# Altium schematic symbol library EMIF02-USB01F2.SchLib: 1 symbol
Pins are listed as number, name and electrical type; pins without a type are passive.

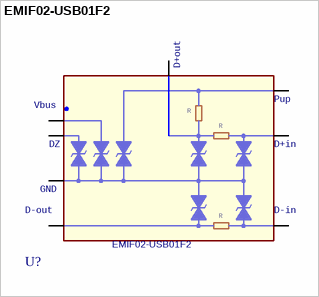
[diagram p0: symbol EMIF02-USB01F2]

## EMIF02-USB01F2
designator U?
footprint ST_CSP08N49P5X3_127X197X65
pins: A1 Vbus, A3 Pup, B2 DZ, C1 D+out, C3 D+in, D2 GND, E1 D-out, E3 D-in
